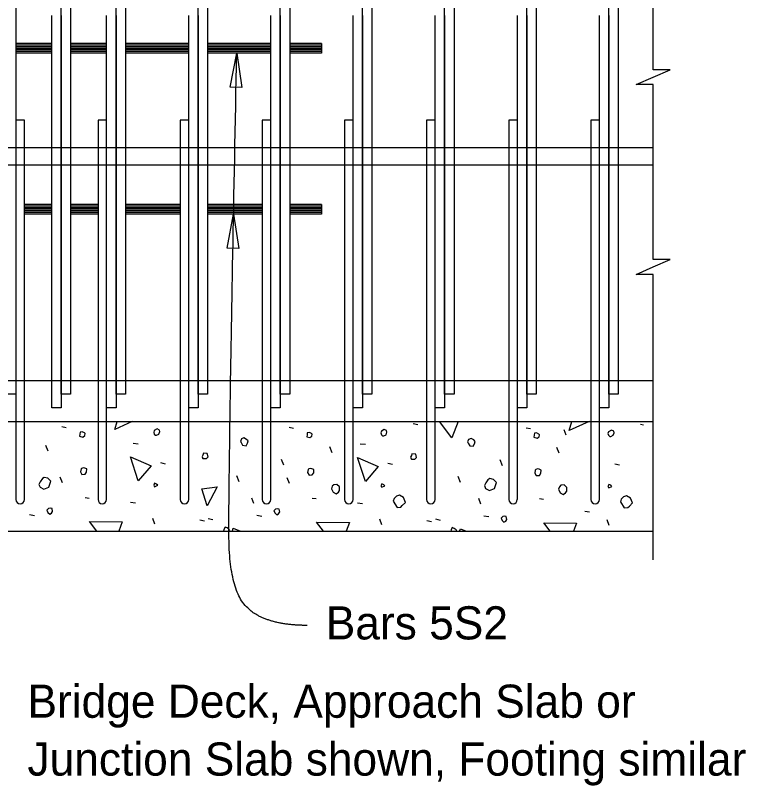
# Model space of a CAD drawing. Extents: x 120588.1 to 120659.6, y 120683.4 to 120715.5.
# Drawn here: x 120603.786 to 120608.231, y 120694.206 to 120698.892 of the extents above; entities that cross this region are included whole.
import ezdxf

# ---------------------------------------------------------------- set-up
doc = ezdxf.new("R2010")
doc.units = 0
for name, color, linetype in [('Dimension', 7, 'Continuous'), ('Patterning', 7, 'Continuous'), ('SheetBorder_dp', 7, 'Continuous'), ('SheetLines_dp', 7, 'Continuous'), ('SupstrConc', 7, 'Continuous')]:
    doc.layers.add(name, color=color, linetype=linetype)

msp = doc.modelspace()

# ---------------------------------------------------------------- linework, layer by layer
at = {"layer": 'Dimension'}
for p, q in [((120604.0693, 120696.3901), (120604.0959, 120696.3848)), ((120605.4517, 120696.3865), (120605.4783, 120696.3812)), ((120606.2083, 120696.4077), (120606.2349, 120696.4024)), ((120606.8955, 120696.383), (120606.922, 120696.3777)), ((120607.1382, 120696.337), (120607.1258, 120696.3706)), ((120607.5907, 120696.4042), (120607.6099, 120696.4004)), ((120604.5025, 120696.2893), (120604.5343, 120696.2858)), ((120605.8848, 120696.2858), (120605.9167, 120696.2822)), ((120603.9863, 120696.24), (120603.9721, 120696.2753)), ((120605.7134, 120696.231), (120605.6992, 120696.2663)), ((120607.0958, 120696.2274), (120607.0816, 120696.2628)), ((120605.4202, 120696.155), (120605.4061, 120696.1903)), ((120606.7511, 120696.1514), (120606.7369, 120696.1868)), ((120604.6704, 120696.1709), (120604.6987, 120696.1638)), ((120606.0528, 120696.1673), (120606.0811, 120696.1603)), ((120607.4352, 120696.1638), (120607.4635, 120696.1567)), ((120605.1478, 120696.0542), (120605.1336, 120696.0895)), ((120604.0729, 120696.0471), (120604.0587, 120696.0825)), ((120605.4553, 120696.0436), (120605.4411, 120696.0789)), ((120606.4947, 120696.0507), (120606.4806, 120696.086)), ((120604.2108, 120695.9587), (120604.2355, 120695.9552)), ((120605.2378, 120695.9216), (120605.2255, 120695.9552)), ((120605.5932, 120695.9552), (120605.6179, 120695.9517)), ((120606.6202, 120695.9181), (120606.6079, 120695.9517)), ((120606.9756, 120695.9517), (120607.0003, 120695.9481)), ((120604.4865, 120695.9305), (120604.5166, 120695.9251)), ((120605.8689, 120695.9269), (120605.899, 120695.9216)), ((120607.2513, 120695.8758), (120607.2814, 120695.8705)), ((120603.8731, 120695.8544), (120603.9032, 120695.8491)), ((120604.635, 120695.7961), (120604.6227, 120695.8297)), ((120604.909, 120695.8226), (120604.9373, 120695.8155)), ((120604.9603, 120695.8315), (120604.9886, 120695.8244)), ((120605.2555, 120695.8509), (120605.2856, 120695.8456)), ((120606.0174, 120695.7926), (120606.0051, 120695.8262)), ((120606.2914, 120695.8191), (120606.3197, 120695.812)), ((120606.3427, 120695.8279), (120606.371, 120695.8208)), ((120606.6379, 120695.8474), (120606.668, 120695.8421)), ((120607.3998, 120695.789), (120607.3874, 120695.8226))]:
    msp.add_line(p, q, dxfattribs=at)
for points in [[(120604.3911, 120696.3724), (120604.4058, 120696.4203)], [(120604.4978, 120696.4203), (120604.3911, 120696.3724)], [(120606.4435, 120696.3211), (120606.3681, 120696.4203)], [(120606.4805, 120696.4203), (120606.4435, 120696.3211)], [(120607.1559, 120696.3653), (120607.1728, 120696.4203)], [(120607.2773, 120696.4203), (120607.2778, 120696.4201), (120607.1559, 120696.3653)], [(120604.6386, 120696.337), (120604.6456, 120696.337), (120604.6598, 120696.3441), (120604.6651, 120696.36), (120604.6633, 120696.3689), (120604.6492, 120696.3759), (120604.6315, 120696.3653), (120604.628, 120696.3547), (120604.6315, 120696.3441), (120604.6386, 120696.337)], [(120606.021, 120696.3335), (120606.028, 120696.3335), (120606.0422, 120696.3406), (120606.0475, 120696.3565), (120606.0457, 120696.3653), (120606.0316, 120696.3724), (120606.0139, 120696.3618), (120606.0104, 120696.3512), (120606.0139, 120696.3406), (120606.021, 120696.3335)], [(120604.1772, 120696.3317), (120604.1966, 120696.3264), (120604.209, 120696.3353), (120604.2108, 120696.3476), (120604.2072, 120696.3512), (120604.1931, 120696.3582), (120604.1807, 120696.3565), (120604.1789, 120696.3441), (120604.1772, 120696.3317)], [(120605.5596, 120696.3282), (120605.579, 120696.3229), (120605.5914, 120696.3317), (120605.5932, 120696.3441), (120605.5896, 120696.3476), (120605.5755, 120696.3547), (120605.5631, 120696.3529), (120605.5613, 120696.3406), (120605.5596, 120696.3282)], [(120606.942, 120696.3247), (120606.9614, 120696.3194), (120606.9738, 120696.3282), (120606.9756, 120696.3406), (120606.972, 120696.3441), (120606.9579, 120696.3512), (120606.9455, 120696.3494), (120606.9437, 120696.337), (120606.942, 120696.3247)], [(120607.4034, 120696.33), (120607.4104, 120696.33), (120607.4246, 120696.337), (120607.4299, 120696.3529), (120607.4281, 120696.3618), (120607.414, 120696.3689), (120607.3963, 120696.3582), (120607.3928, 120696.3476), (120607.3963, 120696.337), (120607.4034, 120696.33)], [(120605.1601, 120696.2928), (120605.1689, 120696.2769), (120605.1901, 120696.2734), (120605.199, 120696.2893), (120605.2025, 120696.3034), (120605.1936, 120696.3123), (120605.1777, 120696.3211), (120605.1618, 120696.3158), (120605.1565, 120696.2999), (120605.1601, 120696.2928)], [(120606.5425, 120696.2893), (120606.5513, 120696.2734), (120606.5725, 120696.2699), (120606.5813, 120696.2858), (120606.5849, 120696.2999), (120606.576, 120696.3088), (120606.5601, 120696.3176), (120606.5442, 120696.3123), (120606.5389, 120696.2964), (120606.5425, 120696.2893)], [(120604.5343, 120696.0595), (120604.4865, 120696.2062), (120604.6121, 120696.1514), (120604.5343, 120696.0595)], [(120604.928, 120696.1956), (120604.9492, 120696.1956), (120604.9598, 120696.2062), (120604.9545, 120696.2257), (120604.9315, 120696.2274), (120604.928, 120696.2168), (120604.9227, 120696.208), (120604.928, 120696.1956), (120604.9244, 120696.1992)], [(120605.9167, 120696.056), (120605.8689, 120696.2027), (120605.9944, 120696.1479), (120605.9167, 120696.056)], [(120606.1965, 120696.1921), (120606.2177, 120696.1921), (120606.2283, 120696.2027), (120606.223, 120696.2221), (120606.2, 120696.2239), (120606.1965, 120696.2133), (120606.1912, 120696.2045), (120606.1965, 120696.1921), (120606.193, 120696.1956)], [(120604.1825, 120696.1143), (120604.1913, 120696.0984), (120604.2108, 120696.1002), (120604.2196, 120696.1125), (120604.2214, 120696.132), (120604.209, 120696.1373), (120604.2002, 120696.139), (120604.1896, 120696.1355), (120604.186, 120696.132), (120604.1825, 120696.1143)], [(120605.5649, 120696.1108), (120605.5737, 120696.0949), (120605.5932, 120696.0966), (120605.602, 120696.109), (120605.6038, 120696.1284), (120605.5914, 120696.1337), (120605.5826, 120696.1355), (120605.572, 120696.132), (120605.5684, 120696.1284), (120605.5649, 120696.1108)], [(120606.9473, 120696.1072), (120606.9561, 120696.0913), (120606.9756, 120696.0931), (120606.9844, 120696.1055), (120606.9862, 120696.1249), (120606.9738, 120696.1302), (120606.965, 120696.132), (120606.9543, 120696.1284), (120606.9508, 120696.1249), (120606.9473, 120696.1072)], [(120603.9363, 120696.0206), (120603.9593, 120696.0082), (120603.9894, 120696.0206), (120604.0017, 120696.0577), (120603.9841, 120696.0754), (120603.9611, 120696.0807), (120603.9505, 120696.0736), (120603.9381, 120696.0542), (120603.9293, 120696.0383), (120603.9363, 120696.0206)], [(120604.6333, 120696.0241), (120604.6527, 120696.033), (120604.6456, 120696.0401), (120604.6333, 120696.0454), (120604.628, 120696.033), (120604.6333, 120696.0241)], [(120606.6485, 120696.0135), (120606.6715, 120696.0012), (120606.7016, 120696.0135), (120606.7139, 120696.0507), (120606.6962, 120696.0683), (120606.6733, 120696.0736), (120606.6627, 120696.0666), (120606.6503, 120696.0471), (120606.6414, 120696.0312), (120606.6485, 120696.0135)], [(120604.9542, 120695.9075), (120604.9206, 120696.0118), (120605.0143, 120696.0241), (120604.9542, 120695.9075)], [(120605.7098, 120696.0118), (120605.7204, 120695.9906), (120605.7381, 120695.9799), (120605.7523, 120695.9906), (120605.7593, 120696.0012), (120605.7593, 120696.0224), (120605.7434, 120696.0383), (120605.724, 120696.0365), (120605.7151, 120696.0277), (120605.7098, 120696.0118)], [(120606.0157, 120696.0206), (120606.0351, 120696.0294), (120606.028, 120696.0365), (120606.0157, 120696.0418), (120606.0104, 120696.0294), (120606.0157, 120696.0206)], [(120607.0922, 120696.0082), (120607.1028, 120695.987), (120607.1205, 120695.9764), (120607.1347, 120695.987), (120607.1417, 120695.9976), (120607.1417, 120696.0188), (120607.1258, 120696.0347), (120607.1064, 120696.033), (120607.0975, 120696.0241), (120607.0922, 120696.0082)], [(120607.3981, 120696.0171), (120607.4175, 120696.0259), (120607.4104, 120696.033), (120607.3981, 120696.0383), (120607.3928, 120696.0259), (120607.3981, 120696.0171)], [(120606.0864, 120695.9358), (120606.1094, 120695.8986), (120606.1323, 120695.9004), (120606.1412, 120695.9092), (120606.1606, 120695.9287), (120606.1482, 120695.9587), (120606.1235, 120695.9729), (120606.1058, 120695.9658), (120606.0917, 120695.9517), (120606.0864, 120695.9358)], [(120607.4688, 120695.9322), (120607.4917, 120695.8951), (120607.5147, 120695.8969), (120607.5236, 120695.9057), (120607.543, 120695.9251), (120607.5306, 120695.9552), (120607.5059, 120695.9693), (120607.4882, 120695.9623), (120607.4741, 120695.9481), (120607.4688, 120695.9322)], [(120603.9845, 120695.8668), (120603.9951, 120695.8562), (120604.0057, 120695.8633), (120604.0128, 120695.8739), (120604.0092, 120695.8916), (120604.0004, 120695.8933), (120603.988, 120695.8916), (120603.9774, 120695.881), (120603.9845, 120695.8668)], [(120605.3669, 120695.8633), (120605.3775, 120695.8527), (120605.3881, 120695.8597), (120605.3952, 120695.8703), (120605.3916, 120695.888), (120605.3828, 120695.8898), (120605.3704, 120695.888), (120605.3598, 120695.8774), (120605.3669, 120695.8633)], [(120604.2816, 120695.7537), (120604.2373, 120695.812), (120604.437, 120695.8102), (120604.4159, 120695.7537)], [(120605.6613, 120695.7537), (120605.6197, 120695.8085), (120605.8194, 120695.8067), (120605.7996, 120695.7537)], [(120606.7493, 120695.818), (120606.7599, 120695.8074), (120606.7705, 120695.8144), (120606.7776, 120695.825), (120606.774, 120695.8427), (120606.7652, 120695.8445), (120606.7528, 120695.8427), (120606.7422, 120695.8321), (120606.7493, 120695.818)], [(120605.0899, 120695.7537), (120605.0911, 120695.7572), (120605.0858, 120695.766), (120605.0752, 120695.7731), (120605.0628, 120695.7784), (120605.0558, 120695.7643), (120605.0522, 120695.7537)], [(120605.1069, 120695.7537), (120605.1123, 120695.7714), (120605.1569, 120695.7537)], [(120606.4735, 120695.7537), (120606.4682, 120695.7625), (120606.4576, 120695.7696), (120606.4452, 120695.7749), (120606.4382, 120695.7607), (120606.4358, 120695.7537)], [(120606.4904, 120695.7537), (120606.4947, 120695.7678), (120606.5304, 120695.7537)], [(120607.041, 120695.7537), (120607.0021, 120695.8049), (120607.2018, 120695.8032), (120607.1833, 120695.7537)]]:
    msp.add_lwpolyline(points, dxfattribs=at)
at = {"layer": 'SheetBorder_dp'}
for p, q in [((120598.1747, 120698.087), (120607.6672, 120698.087)), ((120598.1747, 120697.9829), (120607.6672, 120697.9829)), ((120598.124, 120696.6703), (120607.6672, 120696.6703)), ((120588.5208, 120696.4203), (120607.6672, 120696.4203)), ((120588.5208, 120695.7537), (120607.6672, 120695.7537))]:
    msp.add_line(p, q, dxfattribs=at)
at = {"layer": 'SheetLines_dp'}
for points in [[(120607.6672, 120698.087), (120607.6672, 120698.4714), (120607.5639, 120698.4714), (120607.6672, 120698.5164), (120607.7706, 120698.5614), (120607.6672, 120698.5614), (120607.6672, 120699.087)], [(120607.6672, 120695.5791), (120607.6672, 120697.3162), (120607.5639, 120697.3162), (120607.6672, 120697.3612), (120607.7706, 120697.4062), (120607.6672, 120697.4062), (120607.6672, 120698.087)]]:
    msp.add_lwpolyline(points, dxfattribs=at)
for points in [[(120605.1335, 120698.6624), (120605.1646, 120698.4535), (120605.094, 120698.4549)], [(120605.1147, 120697.6833), (120605.1458, 120697.4744), (120605.0753, 120697.4758)]]:
    msp.add_lwpolyline(points, close=True, dxfattribs=at)
msp.add_open_spline([(120605.5628, 120695.1802), (120605.3213, 120695.1802), (120605.0932, 120695.3772), (120605.0804, 120696.0037), (120605.1335, 120698.6625)], degree=2, dxfattribs=at)
at = {"layer": 'SupstrConc'}
for p, q in [((120604.0081, 120696.5037), (120604.0081, 120698.8917)), ((120604.0653, 120698.8917), (120604.0653, 120696.5037)), ((120604.3414, 120696.5037), (120604.3414, 120698.8917)), ((120604.3987, 120698.8917), (120604.3987, 120696.5037)), ((120604.8414, 120696.5037), (120604.8414, 120698.8917)), ((120604.8987, 120698.8917), (120604.8987, 120696.5037)), ((120605.3414, 120696.5037), (120605.3414, 120698.8917)), ((120605.3987, 120698.8917), (120605.3987, 120696.5037)), ((120605.8414, 120696.5037), (120605.8414, 120698.8917)), ((120605.8987, 120698.8917), (120605.8987, 120696.5037)), ((120606.3414, 120696.5037), (120606.3414, 120698.8917)), ((120606.3987, 120698.8917), (120606.3987, 120696.5037)), ((120606.8414, 120696.5037), (120606.8414, 120698.8917)), ((120606.8987, 120698.8917), (120606.8987, 120696.5037)), ((120607.3414, 120696.5037), (120607.3414, 120698.8917)), ((120607.3987, 120698.8917), (120607.3987, 120696.5037)), ((120604.0081, 120698.7198), (120603.7893, 120698.7198)), ((120604.3414, 120698.7198), (120604.1226, 120698.7198)), ((120604.8414, 120698.7198), (120604.456, 120698.7198)), ((120605.3414, 120698.7198), (120604.956, 120698.7198)), ((120605.6487, 120698.7198), (120605.456, 120698.7198)), ((120605.6487, 120698.7198), (120605.6487, 120698.6625)), ((120604.0081, 120698.7102), (120603.7893, 120698.7102)), ((120604.0081, 120698.7007), (120603.7893, 120698.7007)), ((120604.0081, 120698.6911), (120603.7893, 120698.6911)), ((120604.0081, 120698.6816), (120603.7893, 120698.6816)), ((120604.0081, 120698.672), (120603.7893, 120698.672)), ((120604.3414, 120698.7102), (120604.1226, 120698.7102)), ((120604.3414, 120698.7007), (120604.1226, 120698.7007)), ((120604.3414, 120698.6911), (120604.1226, 120698.6911)), ((120604.3414, 120698.6816), (120604.1226, 120698.6816)), ((120604.3414, 120698.672), (120604.1226, 120698.672)), ((120604.8414, 120698.7102), (120604.456, 120698.7102)), ((120604.8414, 120698.7007), (120604.456, 120698.7007)), ((120604.8414, 120698.6911), (120604.456, 120698.6911)), ((120604.8414, 120698.6816), (120604.456, 120698.6816)), ((120604.8414, 120698.672), (120604.456, 120698.672)), ((120605.3414, 120698.7102), (120604.956, 120698.7102)), ((120605.3414, 120698.7007), (120604.956, 120698.7007)), ((120605.3414, 120698.6911), (120604.956, 120698.6911)), ((120605.3414, 120698.6816), (120604.956, 120698.6816)), ((120605.3414, 120698.672), (120604.956, 120698.672)), ((120605.6487, 120698.7102), (120605.456, 120698.7102)), ((120605.6487, 120698.7007), (120605.456, 120698.7007)), ((120605.6487, 120698.6911), (120605.456, 120698.6911)), ((120605.6487, 120698.6816), (120605.456, 120698.6816)), ((120605.6487, 120698.672), (120605.456, 120698.672)), ((120604.0081, 120698.6625), (120603.7893, 120698.6625)), ((120604.3414, 120698.6625), (120604.1226, 120698.6625)), ((120604.8414, 120698.6625), (120604.456, 120698.6625)), ((120605.3414, 120698.6625), (120604.956, 120698.6625)), ((120605.6487, 120698.6625), (120605.456, 120698.6625)), ((120603.8414, 120698.2537), (120603.7893, 120698.2537)), ((120603.7893, 120698.2537), (120603.7893, 120695.9464)), ((120603.8414, 120695.9464), (120603.8414, 120698.2537)), ((120604.3414, 120698.2537), (120604.2893, 120698.2537)), ((120604.2893, 120698.2537), (120604.2893, 120695.9464)), ((120604.3414, 120695.9464), (120604.3414, 120698.2537)), ((120604.8414, 120698.2537), (120604.7893, 120698.2537)), ((120604.7893, 120698.2537), (120604.7893, 120695.9464)), ((120604.8414, 120695.9464), (120604.8414, 120698.2537)), ((120605.3414, 120698.2537), (120605.2893, 120698.2537)), ((120605.2893, 120698.2537), (120605.2893, 120695.9464)), ((120605.3414, 120695.9464), (120605.3414, 120698.2537)), ((120605.8414, 120698.2537), (120605.7893, 120698.2537)), ((120605.7893, 120698.2537), (120605.7893, 120695.9464)), ((120605.8414, 120695.9464), (120605.8414, 120698.2537)), ((120606.3414, 120698.2537), (120606.2893, 120698.2537)), ((120606.2893, 120698.2537), (120606.2893, 120695.9464)), ((120606.3414, 120695.9464), (120606.3414, 120698.2537)), ((120606.8414, 120698.2537), (120606.7893, 120698.2537)), ((120606.7893, 120698.2537), (120606.7893, 120695.9464)), ((120606.8414, 120695.9464), (120606.8414, 120698.2537)), ((120607.3414, 120698.2537), (120607.2893, 120698.2537)), ((120607.2893, 120698.2537), (120607.2893, 120695.9464)), ((120607.3414, 120695.9464), (120607.3414, 120698.2537)), ((120604.0081, 120697.7406), (120603.8414, 120697.7406)), ((120604.0081, 120697.7311), (120603.8414, 120697.7311)), ((120604.2893, 120697.7406), (120604.1226, 120697.7406)), ((120604.2893, 120697.7311), (120604.1226, 120697.7311)), ((120604.7893, 120697.7406), (120604.456, 120697.7406)), ((120604.7893, 120697.7311), (120604.456, 120697.7311)), ((120605.2893, 120697.7406), (120604.956, 120697.7406)), ((120605.2893, 120697.7311), (120604.956, 120697.7311)), ((120605.6487, 120697.7406), (120605.456, 120697.7406)), ((120605.6487, 120697.7311), (120605.456, 120697.7311)), ((120605.6487, 120697.7406), (120605.6487, 120697.6833)), ((120604.0081, 120697.7215), (120603.8414, 120697.7215)), ((120604.0081, 120697.712), (120603.8414, 120697.712)), ((120604.0081, 120697.7024), (120603.8414, 120697.7024)), ((120604.0081, 120697.6929), (120603.8414, 120697.6929)), ((120604.0081, 120697.6833), (120603.8414, 120697.6833)), ((120604.2893, 120697.7215), (120604.1226, 120697.7215)), ((120604.2893, 120697.712), (120604.1226, 120697.712)), ((120604.2893, 120697.7024), (120604.1226, 120697.7024)), ((120604.2893, 120697.6929), (120604.1226, 120697.6929)), ((120604.2893, 120697.6833), (120604.1226, 120697.6833)), ((120604.7893, 120697.7215), (120604.456, 120697.7215)), ((120604.7893, 120697.712), (120604.456, 120697.712)), ((120604.7893, 120697.7024), (120604.456, 120697.7024)), ((120604.7893, 120697.6929), (120604.456, 120697.6929)), ((120604.7893, 120697.6833), (120604.456, 120697.6833)), ((120605.2893, 120697.7215), (120604.956, 120697.7215)), ((120605.2893, 120697.712), (120604.956, 120697.712)), ((120605.2893, 120697.7024), (120604.956, 120697.7024)), ((120605.2893, 120697.6929), (120604.956, 120697.6929)), ((120605.2893, 120697.6833), (120604.956, 120697.6833)), ((120605.6487, 120697.7215), (120605.456, 120697.7215)), ((120605.6487, 120697.712), (120605.456, 120697.712)), ((120605.6487, 120697.7024), (120605.456, 120697.7024)), ((120605.6487, 120697.6929), (120605.456, 120697.6929)), ((120605.6487, 120697.6833), (120605.456, 120697.6833)), ((120604.0653, 120696.5037), (120604.0081, 120696.5037)), ((120604.3987, 120696.5037), (120604.3414, 120696.5037)), ((120604.8987, 120696.5037), (120604.8414, 120696.5037)), ((120605.3987, 120696.5037), (120605.3414, 120696.5037)), ((120605.8987, 120696.5037), (120605.8414, 120696.5037)), ((120606.3987, 120696.5037), (120606.3414, 120696.5037)), ((120606.8987, 120696.5037), (120606.8414, 120696.5037)), ((120607.3987, 120696.5037), (120607.3414, 120696.5037))]:
    msp.add_line(p, q, dxfattribs=at)
for points in [[(120603.732, 120704.2537), (120603.7893, 120704.2537), (120603.7893, 120696.587), (120603.732, 120696.587)], [(120604.0653, 120704.2537), (120604.1226, 120704.2537), (120604.1226, 120696.587), (120604.0653, 120696.587)], [(120604.3987, 120704.2537), (120604.456, 120704.2537), (120604.456, 120696.587), (120604.3987, 120696.587)], [(120604.8987, 120704.2537), (120604.956, 120704.2537), (120604.956, 120696.587), (120604.8987, 120696.587)], [(120605.8987, 120704.2537), (120605.956, 120704.2537), (120605.956, 120696.587), (120605.8987, 120696.587)], [(120606.3987, 120704.2537), (120606.456, 120704.2537), (120606.456, 120696.587), (120606.3987, 120696.587)], [(120606.8987, 120704.2537), (120606.956, 120704.2537), (120606.956, 120696.587), (120606.8987, 120696.587)], [(120607.3987, 120704.2537), (120607.456, 120704.2537), (120607.456, 120696.587), (120607.3987, 120696.587)]]:
    msp.add_lwpolyline(points, close=True, dxfattribs=at)
msp.add_lwpolyline([(120605.456, 120696.587), (120605.3987, 120696.587), (120605.3987, 120704.2537), (120605.456, 120704.2537), (120605.456, 120696.587)], dxfattribs=at)
for centre in [(120603.8153, 120695.9464), (120604.3153, 120695.9464), (120604.8153, 120695.9464), (120605.3153, 120695.9464), (120605.8153, 120695.9464), (120606.3153, 120695.9464), (120606.8153, 120695.9464), (120607.3153, 120695.9464)]:
    msp.add_arc(centre, 0.026, 180, 0, dxfattribs=at)

# ---------------------------------------------------------------- texts
at = {"layer": 'Patterning'}
msp.add_text('Bars 5S2', height=0.2016, dxfattribs=at).set_placement((120605.6754, 120695.0949))
at = {"layer": 'SheetLines_dp'}
for s, p in [('Bridge Deck, Approach Slab or ', (120603.8598, 120694.6183)), ('Junction Slab shown, Footing similar', (120603.8598, 120694.2663))]:
    msp.add_text(s, height=0.2016, dxfattribs=at).set_placement(p)

doc.saveas('drawing.dxf')
